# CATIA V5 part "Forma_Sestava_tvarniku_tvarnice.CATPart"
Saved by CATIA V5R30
Part number: Forma_Sestava_tvarniku_tvarnice
Publications: "__DrillHole_Ejector_E1710_2.1_Tvarnik_tvarnice.1", "__DrillHole_Ejector_E1710_3.1_Tvarnik_tvarnice.1", "__DrillHole_Ejector_E1710_4.1_Tvarnik_tvarnice.1", "__DrillHole_Ejector_E1710_5.1_Tvarnik_tvarnice.1", "__DrillHole_Ejector_E1710_6.1_Tvarnik_tvarnice.1", "__DrillHole_Ejector_E1710_7.1_Tvarnik_tvarnice_1.1", "__DrillHole_Ejector_E1710_8.1_Tvarnik_tvarnice_1.1", "__DrillHole_Ejector_E1710_9.1_Tvarnik_tvarnice_1.1", "__DrillHole_Ejector_E1710_10.1_Tvarnik_tvarnice_1.1", "__DrillHole_Ejector_E1710_11.1_Tvarnik_tvarnice_1.1", "__DrillHole_Ejector_E1710_1.1_Tvarnik_tvarnice.1", "__DrillHole_Ejector_E1710_13.1_Tvarnik_tvarnice.1", "__DrillHole_Ejector_E1710_14.1_Tvarnik_tvarnice.1", "__DrillHole_Ejector_E1710_15.1_Tvarnik_tvarnice.1", "__DrillHole_Ejector_E1710_16.1_Tvarnik_tvarnice.1", "__DrillHole_Ejector_E1710_17.1_Tvarnik_tvarnice_1.1", "__DrillHole_Ejector_E1710_18.1_Tvarnik_tvarnice_1.1", "__DrillHole_Ejector_E1710_19.1_Tvarnik_tvarnice_1.1", "__DrillHole_Ejector_E1710_20.1_Tvarnik_tvarnice_1.1", "__DrillHole_Ejector_E1710_21.1_Tvarnik_tvarnice_1.1", "__DrillHole_Ejector_E1710_23.1_Tvarnik_tvarnice.1", "__DrillHole_Ejector_E1710_24.1_Tvarnik_tvarnice.1", "__DrillHole_Ejector_E1710_25.1_Tvarnik_tvarnice.1", "__DrillHole_Ejector_E1710_26.1_Tvarnik_tvarnice.1", "__DrillHole_Ejector_E1710_27.1_Tvarnik_tvarnice.1", "__DrillHole_Ejector_E1710_28.1_Tvarnik_tvarnice.1", "__DrillHole_Ejector_E1710_29.1_Tvarnik_tvarnice.1", "__DrillHole_Ejector_E1710_31.1_Tvarnik_tvarnice_1.1", "__DrillHole_Ejector_E1710_32.1_Tvarnik_tvarnice_1.1", "__DrillHole_Ejector_E1710_33.1_Tvarnik_tvarnice_1.1", "__DrillHole_Ejector_E1710_34.1_Tvarnik_tvarnice_1.1", "__DrillHole_Ejector_E1710_35.1_Tvarnik_tvarnice_1.1", "__DrillHole_Ejector_E1710_36.1_Tvarnik_tvarnice_1.1", "__DrillHole_Ejector_E1710_37.1_Tvarnik_tvarnice_1.1", "__DrillHole_Ejector_E1710_1.2_Tvarnik_tvarnice_1.1", "__DrillHole_Ejector_E1710_2.2_Tvarnik_tvarnice_1.1", "__DrillHole_Ejector_E1710_3.2_Tvarnik_tvarnice_1.1", "__DrillHole_Ejector_E1710_4.2_Tvarnik_tvarnice_1.1"
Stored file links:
  E:\Bakalarka\Model\Forma_v7\Forma_Sestava_tvarniku_tvarnice.CATPart
  E:\Bakalarka\Model\Forma_v7\Forma.CATProduct
  E:\Bakalarka\Model\Forma_v7\TlgItf_Sestava_tvarniku_tvarnice.CATProduct

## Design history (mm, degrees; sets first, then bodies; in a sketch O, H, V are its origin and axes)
Body1 (main body)
Body2 "__DrillHole"
  Solid1: linked copy from another document
Body3 "__DrillHole"
  Solid2: linked copy from another document
Body4 "__DrillHole"
  Solid3: linked copy from another document
Body5 "__DrillHole"
  Solid4: linked copy from another document
Body6 "__DrillHole"
  Solid5: linked copy from another document
Body7 "__DrillHole"
  Solid6: linked copy from another document
Body8 "__DrillHole"
  Solid7: linked copy from another document
Body9 "__DrillHole"
  Solid8: linked copy from another document
Body10 "__DrillHole"
  Solid9: linked copy from another document
Body11 "__DrillHole"
  Solid10: linked copy from another document
Body12 "__DrillHole"
  Solid11: linked copy from another document
Body13 "__DrillHole"
  Solid12: linked copy from another document
Body14 "__DrillHole"
  Solid13: linked copy from another document
Body15 "__DrillHole"
  Solid14: linked copy from another document
Body16 "__DrillHole"
  Solid15: linked copy from another document
Body17 "__DrillHole"
  Solid16: linked copy from another document
Body18 "__DrillHole"
  Solid17: linked copy from another document
Body19 "__DrillHole"
  Solid18: linked copy from another document
Body20 "__DrillHole"
  Solid19: linked copy from another document
Body21 "__DrillHole"
  Solid20: linked copy from another document
Body22 "__DrillHole"
  Solid21: linked copy from another document
Body23 "__DrillHole"
  Solid22: linked copy from another document
Body24 "__DrillHole"
  Solid23: linked copy from another document
Body25 "__DrillHole"
  Solid24: linked copy from another document
Body26 "__DrillHole"
  Solid25: linked copy from another document
Body27 "__DrillHole"
  Solid26: linked copy from another document
Body28 "__DrillHole"
  Solid27: linked copy from another document
Body29 "__DrillHole"
  Solid28: linked copy from another document
Body30 "__DrillHole"
  Solid29: linked copy from another document
Body31 "__DrillHole"
  Solid30: linked copy from another document
Body32 "__DrillHole"
  Solid31: linked copy from another document
Body33 "__DrillHole"
  Solid32: linked copy from another document
Body34 "__DrillHole"
  Solid33: linked copy from another document
Body35 "__DrillHole"
  Solid34: linked copy from another document
Body36 "__DrillHole"
  Solid35: linked copy from another document
Body37 "__DrillHole"
  Solid36: linked copy from another document
Body38 "__DrillHole"
  Solid37: linked copy from another document
Body39 "__DrillHole"
  Solid38: linked copy from another document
